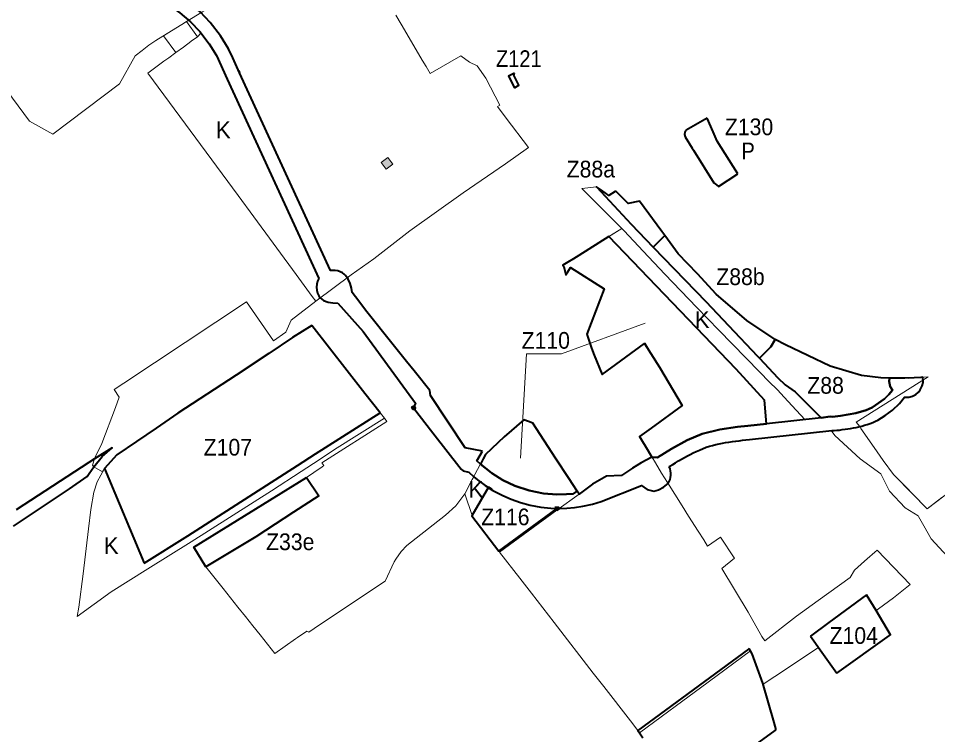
# Model space of a CAD drawing. Extents: x -650276 to -642489, y -1074425 to -1066658.
# Drawn here: x -648043 to -646722, y -1072629 to -1071600 of the extents above; entities that cross this region are included whole.
import ezdxf

# ---------------------------------------------------------------- set-up
doc = ezdxf.new("R2010")
doc.units = 0
doc.header["$LTSCALE"] = 9.6
doc.header["$PDMODE"] = 32
doc.header["$PDSIZE"] = 4.8
for name, color, linetype, lineweight in [('1', 7, 'Continuous', 13), ('43', 7, 'Continuous', 13), ('44', 7, 'Continuous', 40), ('45', 7, 'Continuous', 40), ('46', 7, 'Continuous', 13), ('47', 7, 'Continuous', 13), ('60', 7, 'Continuous', 35)]:
    doc.layers.add(name, color=color, linetype=linetype, lineweight=lineweight)

msp = doc.modelspace()

# ---------------------------------------------------------------- hatches: boundary and pattern name
at = {"layer": '1'}
msp.add_hatch(color=256, dxfattribs=at).paths.add_polyline_path([(-647515.13, -1071817.13), (-647505.54, -1071809.91), (-647512.76, -1071800.33), (-647522.34, -1071807.54)])

# ---------------------------------------------------------------- linework, layer by layer
for points in [[(-648086.68, -1071669.2), (-648027.69, -1071748), (-647993.77, -1071766.7), (-647898.22, -1071694.24), (-647875.8, -1071654.22), (-647865.84, -1071646.51), (-647856.11, -1071638.98), (-647845.78, -1071631.97), (-647823.51, -1071618.28), (-647808.56, -1071609.1), (-647801.84, -1071604.97), (-647778.84, -1071590.84), (-647756.17, -1071577.89), (-647694.65, -1071531.5), (-647658.2, -1071504.43), (-647650.97, -1071499.11), (-647639.66, -1071490.78), (-647632, -1071487.54)], [(-647501.11, -1071595.45), (-647493.6, -1071608.5), (-647471.62, -1071645.45), (-647463.05, -1071660.13), (-647457.62, -1071669.57), (-647451.72, -1071679.52), (-647407.49, -1071654.3), (-647395.07, -1071663.45), (-647384.28, -1071668.72), (-647371.48, -1071686.13), (-647351.64, -1071725.05), (-647355.11, -1071727.05), (-647342.27, -1071743.92), (-647310.23, -1071786.05), (-647343.45, -1071809.51), (-647404.5, -1071850.92), (-647480.76, -1071905.45), (-647532.55, -1071945.64), (-647565.32, -1071968.57), (-647616.12, -1072006.7), (-647651.4, -1072034), (-647659.22, -1072050.95), (-647676.99, -1072063.58), (-647715.48, -1072007.5), (-647891.9, -1072124.43), (-647905.91, -1072133.72), (-647898.74, -1072144.71), (-647903.78, -1072159.62), (-647923.47, -1072211.02), (-647933.11, -1072230.84), (-647933.95, -1072233.18), (-647936.91, -1072242.12), (-647934.9, -1072244.55), (-647922.401, -1072251.989), (-647919.68, -1072247.09), (-647901.91, -1072227.6), (-647845.58, -1072188.94), (-647814.58, -1072167.67), (-647730.53, -1072112.84), (-647683.63, -1072081.94), (-647649.76, -1072059.06), (-647621.97, -1072041.73), (-647545.44, -1072139.35), (-647517.51, -1072174.98), (-647514.05, -1072179.39), (-647607.17, -1072238.79), (-647604.34, -1072242.95), (-647607.02, -1072244.69), (-647619.06, -1072252.92), (-647629.67, -1072259.82), (-647611.51, -1072286.26), (-647648.09, -1072309.95), (-647688.26, -1072336.06), (-647702.35, -1072345.14), (-647716.62, -1072353.95), (-647730.97, -1072362.6), (-647745.32, -1072371.26), (-647759.68, -1072379.91), (-647774.04, -1072388.57), (-647751.23, -1072417.15), (-647749.17, -1072419.72), (-647738.56, -1072433.02), (-647727.94, -1072446.33), (-647717.32, -1072459.63), (-647706.7, -1072472.93), (-647696.09, -1072486.23), (-647685.46, -1072499.54), (-647674.85, -1072512.84), (-647645.17, -1072492.03), (-647642.28, -1072490), (-647628.89, -1072480.61), (-647626.19, -1072482.38), (-647610.9, -1072471.66), (-647516.33, -1072408.76), (-647503.64, -1072381.33), (-647501.08, -1072377.59), (-647493.33, -1072366.28), (-647485.08, -1072357.8), (-647471.76, -1072347.31), (-647429.53, -1072314.04), (-647415.04, -1072300.91), (-647401.88, -1072283.4), (-647395.732, -1072271.563), (-647391.3, -1072263.04), (-647372.1, -1072226.89), (-647345.589, -1072201.74), (-647317.33, -1072176.99), (-647310.33, -1072179.58), (-647304.32, -1072181.81), (-647271.38, -1072232.23), (-647251.85, -1072262.12), (-647240.55, -1072279.42)], [(-647801.84, -1071604.97), (-647808.56, -1071609.1), (-647823.51, -1071618.28), (-647835.178, -1071625.453), (-647817.33, -1071649.51)], [(-647817.33, -1071649.51), (-647806.35, -1071641.47), (-647795.76, -1071633.72), (-647794.98, -1071633.15), (-647786.1, -1071626.65), (-647801.84, -1071604.97)], [(-647119.07, -1072253.56), (-647128.07, -1072238.83), (-647138.65, -1072221.5), (-647151.05, -1072201.21), (-647134.17, -1072188.95), (-647089.54, -1072156.53), (-647105.82, -1072129.3), (-647122.33, -1072101.34), (-647142.77, -1072067), (-647143.76, -1072067.69), (-647204.38, -1072111.87), (-647216.23, -1072084.14), (-647219.64, -1072074.29), (-647226.41, -1072054.11), (-647201.53, -1071988.71), (-647249.92, -1071958.12), (-647253.85, -1071964.38), (-647256.53, -1071968.64), (-647259.7, -1071957.06), (-647261.12, -1071954.82), (-647253.67, -1071950.76), (-647176.32, -1071902.3), (-647194.128, -1071884.447), (-647209.94, -1071868.59), (-647233.81, -1071844.66), (-647212.66, -1071842.15), (-647194.96, -1071854.93), (-647184.81, -1071848.61), (-647167.15, -1071866.22), (-647151.07, -1071863.08), (-647095.51, -1071938.39), (-647067.53, -1071967.54), (-647040.89, -1071996.58), (-646996.8, -1072034.35), (-646956.04, -1072061.95), (-646876.83, -1072100.12), (-646868.61, -1072102.6), (-646832.01, -1072113.66), (-646806.87, -1072116.94), (-646771.31, -1072117.49), (-646763.93, -1072117.61), (-646736.02, -1072115.38), (-646839.631, -1072180.339), (-646834.279, -1072186.818), (-646832.718, -1072189.697), (-646813.516, -1072217.078), (-646800.76, -1072235.668), (-646785.958, -1072255.505), (-646766.842, -1072275.063)], [(-646737.449, -1072305.019), (-646643.55, -1072233.5), (-646593.85, -1072195.48), (-646592.2, -1072196.17), (-646539.94, -1072160.83), (-646555.49, -1072138.17), (-646563.11, -1072143.03), (-646577.08, -1072118.7)], [(-647240.55, -1072279.42), (-647237.6, -1072283.78), (-647269.52, -1072307.17), (-647351.86, -1072367.52), (-647323.06, -1072404.65), (-647306.23, -1072426.35), (-647273.75, -1072468.22), (-647217.32, -1072540.99), (-647202.22, -1072560.47), (-647164.01, -1072609.74), (-647153.2, -1072623.68), (-647150.75, -1072626.84), (-647088.39, -1072580.86), (-647063.38, -1072562.42), (-646991.24, -1072509.24), (-646989.01, -1072513.62), (-646973.68, -1072555.68), (-646973.066, -1072556.947), (-646956.61, -1072546.07), (-646893.64, -1072504.45), (-646898.1, -1072498.02), (-646905.18, -1072487.8), (-646878.91, -1072468.54), (-646850.71, -1072447.86), (-646824.42, -1072428.58), (-646810.77, -1072451.09), (-646807.63, -1072448.81), (-646785.86, -1072433.01), (-646761.676, -1072413.971), (-646809.315, -1072364.299), (-646812.476, -1072367.094), (-646823.75, -1072377.06), (-646827.49, -1072380.37), (-646841.82, -1072393.03), (-646848.37, -1072403.6), (-646893.97, -1072436.54), (-646925.22, -1072459.03), (-646970.68, -1072494.71), (-646975.12, -1072488.48), (-646994.61, -1072453.36), (-647032.76, -1072390.75), (-647014.14, -1072376.08), (-647014.73, -1072375.41), (-647034.39, -1072345.9), (-647052.94, -1072358.64), (-647058.5, -1072349.78), (-647066.38, -1072337.31), (-647080.27, -1072315.34), (-647089.59, -1072300.59), (-647110.55, -1072267.42), (-647119.07, -1072253.56)], [(-646766.842, -1072275.063), (-646758.684, -1072283.41), (-646737.449, -1072305.019)]]:
    msp.add_lwpolyline(points, dxfattribs=at)
msp.add_lwpolyline([(-647515.13, -1071817.13), (-647505.54, -1071809.91), (-647512.76, -1071800.33), (-647522.34, -1071807.54)], close=True, dxfattribs=at)
at = {"layer": '44'}
msp.add_line((-646978.602, -1072088.66), (-646951.95, -1072116.84), dxfattribs=at)
for points in [[(-647725.629, -1071678.373), (-647735.352, -1071657.117), (-647741.34, -1071644.028), (-647753.065, -1071625.201), (-647767.784, -1071606.225), (-647782.408, -1071590.847), (-647798.911, -1071576.526), (-647817.375, -1071563.458), (-647834.953, -1071553.406)], [(-647847.103, -1071569.497), (-647828.141, -1071580.34), (-647811.272, -1071592.28), (-647796.24, -1071605.324), (-647782.97, -1071619.278)], [(-647782.97, -1071619.278), (-647769.498, -1071636.647), (-647758.994, -1071653.513), (-647743.48, -1071687.426), (-647611.514, -1071974.086)], [(-647563.77, -1071994.38), (-647564.751, -1071987.939), (-647566.62, -1071981.3), (-647569.422, -1071974.943), (-647573.283, -1071969.627), (-647575.415, -1071967.709), (-647577.881, -1071965.979), (-647581.036, -1071964.346), (-647584.363, -1071963.196), (-647588.064, -1071962.51), (-647591.518, -1071962.387), (-647594.731, -1071962.714), (-647725.614, -1071678.405), (-647726.774, -1071675.885), (-647725.629, -1071678.373)], [(-647611.514, -1071974.086), (-647613.455, -1071978.031), (-647614.654, -1071982.238), (-647615.083, -1071986.65), (-647614.76, -1071990.762), (-647613.637, -1071995.081), (-647611.779, -1071999.069), (-647609.808, -1072001.962)], [(-647542.57, -1072021.99), (-647558.97, -1072000.62), (-647563.77, -1071994.38)], [(-647609.808, -1072001.962), (-647604.924, -1072005.628), (-647598.384, -1072007.852), (-647591.564, -1072009.255), (-647584.202, -1072009.747)], [(-647584.202, -1072009.747), (-647547.916, -1072050.439), (-647473.022, -1072153.375), (-647475.57, -1072159.74)], [(-647452.23, -1072134.91), (-647472.86, -1072109.13), (-647474.72, -1072106.81), (-647485.6, -1072093.2), (-647504.73, -1072069.29), (-647542.57, -1072021.99)], [(-646790.432, -1072129.195), (-646791.977, -1072122.305), (-646791.84, -1072117.172), (-646804.27, -1072116.98), (-646832.01, -1072113.66), (-646876.83, -1072100.12), (-646941.054, -1072069.172), (-646956.04, -1072061.95), (-646962.041, -1072072.379), (-646978.602, -1072088.66)], [(-646951.95, -1072116.84), (-646941.45, -1072126.84), (-646927.14, -1072136.74), (-646891.05, -1072172.79), (-646890.044, -1072174.056), (-646876.712, -1072172.592), (-646873.495, -1072172.799), (-646862.09, -1072171.444), (-646840.102, -1072167.623), (-646825.169, -1072163.164), (-646816.74, -1072159.571), (-646799, -1072147), (-646792.58, -1072140.847), (-646787.481, -1072134.643), (-646790.432, -1072129.195)], [(-646808.466, -1072177.78), (-646797.713, -1072171.151), (-646787.223, -1072163.402), (-646777.129, -1072153.576), (-646770.057, -1072144.677), (-646763.959, -1072144.535), (-646758.736, -1072143.137), (-646753.929, -1072140.612), (-646750.164, -1072137.467), (-646747.39, -1072134.069), (-646744.554, -1072128.415), (-646743.411, -1072123.612), (-646743.596, -1072115.985), (-646746.547, -1072116.221), (-646756.298, -1072117), (-646769.668, -1072117.517), (-646783.449, -1072117.302), (-646791.84, -1072117.172)], [(-646791.84, -1072117.172), (-646791.977, -1072122.305), (-646790.432, -1072129.195)], [(-647376.68, -1072222.29), (-647401.221, -1072217.342), (-647451.21, -1072142.08), (-647452.23, -1072134.91)], [(-646790.432, -1072129.195), (-646787.481, -1072134.643), (-646792.58, -1072140.847), (-646799, -1072147), (-646816.74, -1072159.571), (-646825.169, -1072163.164), (-646840.102, -1072167.623), (-646862.09, -1072171.444), (-646873.495, -1072172.799), (-646876.712, -1072172.592), (-646890.044, -1072174.056), (-646968.503, -1072182.672)], [(-647475.57, -1072159.74), (-647447.73, -1072195.72), (-647407.34, -1072247.93)], [(-646835.538, -1072187.097), (-646831.517, -1072186.103), (-646827.501, -1072184.997), (-646823.496, -1072183.769), (-646819.509, -1072182.408), (-646815.549, -1072180.906), (-646811.621, -1072179.254), (-646808.466, -1072177.78)], [(-646968.503, -1072182.672), (-646995.137, -1072185.597), (-647010.148, -1072187.308), (-647035.515, -1072191.104), (-647060.973, -1072197.439), (-647082.249, -1072206.591), (-647104.989, -1072219.005), (-647124.81, -1072231.168), (-647133, -1072230.754), (-647148.71, -1072238.76)], [(-647017.46, -1072208.427), (-647012.612, -1072207.773), (-647007.734, -1072207.162), (-647002.826, -1072206.583), (-646997.894, -1072206.024), (-646992.937, -1072205.475), (-646874.517, -1072192.471), (-646871.271, -1072192.675)], [(-646871.271, -1072192.675), (-646867.371, -1072192.234), (-646867.32, -1072192.228), (-646863.448, -1072191.771), (-646859.506, -1072191.276), (-646855.545, -1072190.741), (-646851.567, -1072190.155)], [(-646851.567, -1072190.155), (-646847.575, -1072189.507), (-646843.569, -1072188.789), (-646843.535, -1072188.782), (-646839.556, -1072187.988), (-646835.538, -1072187.097)], [(-648050.276, -1072330.025), (-647969.894, -1072276.479), (-647944.45, -1072258.458), (-647941.77, -1072254.45), (-647934.9, -1072244.55), (-647923.16, -1072229.85), (-647908.5, -1072217.29), (-647933.95, -1072233.18), (-647942.21, -1072238.54), (-648046.69, -1072306.3)], [(-647108.131, -1072244.373), (-647103.164, -1072241.306), (-647098.944, -1072238.718), (-647094.737, -1072236.177), (-647090.531, -1072233.695), (-647086.322, -1072231.285), (-647082.102, -1072228.962), (-647077.867, -1072226.739), (-647073.611, -1072224.631), (-647069.33, -1072222.651), (-647064.868, -1072220.746), (-647054.841, -1072216.479), (-647050.344, -1072215.107), (-647045.786, -1072213.858), (-647041.174, -1072212.723), (-647036.512, -1072211.693), (-647031.807, -1072210.758), (-647027.061, -1072209.91), (-647022.278, -1072209.136), (-647017.46, -1072208.427)], [(-647240.55, -1072279.42), (-647246.206, -1072283.328), (-647255.671, -1072284.192), (-647269.579, -1072284.489), (-647288.769, -1072283.003), (-647309.416, -1072278.875), (-647330.032, -1072271.935), (-647347.382, -1072263.623), (-647363.317, -1072253.632), (-647363.786, -1072253.254), (-647379.422, -1072240.675), (-647384.567, -1072236.256), (-647376.68, -1072222.29)], [(-647148.71, -1072238.76), (-647160.91, -1072246.82), (-647176.7, -1072257.24), (-647198.3, -1072258.09), (-647218.35, -1072269.67), (-647237.6, -1072283.78), (-647240.55, -1072279.42)], [(-647407.34, -1072247.93), (-647404.45, -1072250.66), (-647396.25, -1072252.14), (-647389.072, -1072258.845)], [(-647389.072, -1072258.845), (-647383.813, -1072263.219), (-647372.858, -1072271.363), (-647361.521, -1072278.584), (-647347.369, -1072286.111)], [(-647205.975, -1072294.599), (-647148.171, -1072271.47), (-647139.697, -1072277.484), (-647130.12, -1072279.44), (-647123.774, -1072277.899)], [(-647123.774, -1072277.899), (-647116.323, -1072273.885), (-647109.812, -1072268.588)], [(-647347.369, -1072286.111), (-647335.382, -1072291.341), (-647321.953, -1072296.073), (-647308.157, -1072299.786), (-647292.715, -1072302.646), (-647278.108, -1072304.147), (-647271.395, -1072304.452), (-647269.52, -1072307.17), (-647265.793, -1072304.439)], [(-647265.793, -1072304.439), (-647255.16, -1072304.123), (-647244.428, -1072303.192), (-647232.368, -1072301.4), (-647218.5, -1072298.335), (-647205.975, -1072294.599)]]:
    msp.add_lwpolyline(points, dxfattribs=at)
msp.add_arc((-647130.12, -1072255.012), 24.428, 326.23773, 25.81772, dxfattribs=at)
msp.add_point((-647475.57, -1072159.74), dxfattribs=at)
at = {"layer": '45'}
for points in [[(-647330.34, -1071678.82), (-647339.211, -1071683.431), (-647330.73, -1071700.09)], [(-647330.73, -1071700.09), (-647324.21, -1071696.2), (-647331.65, -1071681.7), (-647330.34, -1071678.82)], [(-647053.43, -1071743.63), (-647083.97, -1071760.74), (-647084.95, -1071761.98), (-647085.71, -1071763.75), (-647086.19, -1071766.95), (-647085.25, -1071770.69), (-647074.99, -1071786.99), (-647073.19, -1071789.9), (-647044.12, -1071836.68)], [(-647009.514, -1071823.81), (-647016.12, -1071813.35), (-647039.14, -1071776.9), (-647044.83, -1071763.37), (-647053.43, -1071743.63)], [(-647044.12, -1071836.68), (-647040.2, -1071839.6), (-647037.23, -1071841.82), (-647009.514, -1071823.81)], [(-647184.81, -1071848.61), (-647185.62, -1071849.12), (-647194.96, -1071854.93), (-647205.62, -1071847.24), (-647212.66, -1071842.15), (-647163.08, -1071896.13), (-647131.146, -1071929.146)], [(-647131.146, -1071929.146), (-647114.479, -1071912.479), (-647118.79, -1071906.59), (-647151.07, -1071863.08), (-647167.15, -1071866.22), (-647184.81, -1071848.61)], [(-646996.8, -1072034.35), (-647040.89, -1071996.58), (-647067.53, -1071967.54), (-647095.51, -1071938.39), (-647114.479, -1071912.479), (-647131.146, -1071929.146), (-647101.07, -1071960.24)], [(-647101.07, -1071960.24), (-647055.16, -1072007.74), (-647023.04, -1072041.63), (-646981.35, -1072085.77), (-646978.602, -1072088.66), (-646962.041, -1072072.379), (-646956.04, -1072061.95), (-646996.8, -1072034.35)], [(-647621.97, -1072041.73), (-647649.76, -1072059.06), (-647683.63, -1072081.94), (-647730.53, -1072112.84), (-647814.58, -1072167.67), (-647845.58, -1072188.94), (-647901.91, -1072227.6), (-647919.68, -1072247.09), (-647862.615, -1072383.084)], [(-647523.71, -1072167.071), (-647545.44, -1072139.35), (-647621.97, -1072041.73)], [(-647862.615, -1072383.084), (-647800.2, -1072343.615), (-647642.504, -1072242.974), (-647616.719, -1072226.154), (-647523.71, -1072167.071)], [(-647362.702, -1072277.035), (-647367.686, -1072273.861), (-647391.761, -1072315.201), (-647353.041, -1072365.971), (-647270.701, -1072305.621), (-647266.974, -1072302.89), (-647272.576, -1072302.903)], [(-646824.42, -1072428.58), (-646878.91, -1072468.54), (-646905.18, -1072487.8)], [(-646824.42, -1072428.58), (-646878.91, -1072468.54), (-646905.18, -1072487.8)], [(-646867.283, -1072540.984), (-646791.569, -1072487.198), (-646790.354, -1072486.136), (-646810.77, -1072451.09), (-646824.42, -1072428.58)], [(-646867.283, -1072540.984), (-646791.569, -1072487.198), (-646790.354, -1072486.136), (-646810.77, -1072451.09), (-646824.42, -1072428.58)], [(-646905.18, -1072487.8), (-646898.1, -1072498.02), (-646893.64, -1072504.45), (-646867.283, -1072540.984)], [(-646905.18, -1072487.8), (-646898.1, -1072498.02), (-646893.64, -1072504.45), (-646867.283, -1072540.984)], [(-646993.05, -1072505.68), (-646994.2, -1072506.52), (-647153.2, -1072623.68), (-647150.75, -1072626.84), (-647146.21, -1072634.02)], [(-646954.617, -1072622.388), (-646957.5, -1072612.09), (-646973.68, -1072555.68), (-646989.01, -1072513.62), (-646991.24, -1072509.24), (-646993.05, -1072505.68)], [(-647192.069, -1072916.856), (-647177.144, -1072871.095), (-647160.08, -1072833.974), (-647140.764, -1072806.081), (-647083.498, -1072727.769), (-647028.234, -1072676.101), (-646956.061, -1072623.348), (-646954.617, -1072622.388)]]:
    msp.add_lwpolyline(points, dxfattribs=at)
for points in [[(-647226.41, -1072054.11), (-647219.64, -1072074.29), (-647216.23, -1072084.14), (-647204.78, -1072110.92), (-647204.38, -1072111.87), (-647143.76, -1072067.69), (-647122.33, -1072101.34), (-647089.54, -1072156.53), (-647134.17, -1072188.95), (-647151.05, -1072201.21), (-647138.65, -1072221.5), (-647133, -1072230.754), (-647124.81, -1072231.168), (-647104.989, -1072219.005), (-647082.249, -1072206.591), (-647060.973, -1072197.439), (-647035.515, -1072191.104), (-647010.148, -1072187.308), (-646995.137, -1072185.597), (-646968.503, -1072182.672), (-646971.283, -1072148.82), (-647011.762, -1072104.502), (-647194.903, -1071913.941), (-647238.1, -1071941), (-647245.71, -1071945.77), (-647253.67, -1071950.76), (-647261.12, -1071954.82), (-647259.7, -1071957.06), (-647256.53, -1071968.64), (-647253.85, -1071964.38), (-647249.92, -1071958.12), (-647201.53, -1071988.71)], [(-647226.41, -1072054.11), (-647219.64, -1072074.29), (-647216.23, -1072084.14), (-647204.78, -1072110.92), (-647204.38, -1072111.87), (-647143.76, -1072067.69), (-647122.33, -1072101.34), (-647089.54, -1072156.53), (-647134.17, -1072188.95), (-647151.05, -1072201.21), (-647138.65, -1072221.5), (-647133, -1072230.754), (-647124.81, -1072231.168), (-647104.989, -1072219.005), (-647082.249, -1072206.591), (-647060.973, -1072197.439), (-647035.515, -1072191.104), (-647010.148, -1072187.308), (-646995.137, -1072185.597), (-646968.503, -1072182.672), (-646971.283, -1072148.82), (-647011.762, -1072104.502), (-647194.903, -1071913.941), (-647238.1, -1071941), (-647245.71, -1071945.77), (-647253.67, -1071950.76), (-647261.12, -1071954.82), (-647259.7, -1071957.06), (-647256.53, -1071968.64), (-647253.85, -1071964.38), (-647249.92, -1071958.12), (-647201.53, -1071988.71)], [(-647246.563, -1072270.214), (-647251.85, -1072262.12), (-647271.38, -1072232.23), (-647304.32, -1072181.81), (-647310.33, -1072179.58), (-647317.33, -1072176.99), (-647345.42, -1072201.58), (-647372.1, -1072226.89), (-647375.551, -1072233.387), (-647379.422, -1072240.675), (-647363.317, -1072253.632), (-647347.382, -1072263.623), (-647330.032, -1072271.935), (-647309.416, -1072278.875), (-647288.769, -1072283.003), (-647269.579, -1072284.489), (-647255.671, -1072284.192), (-647246.206, -1072283.328), (-647240.55, -1072279.42)], [(-647246.563, -1072270.214), (-647251.85, -1072262.12), (-647271.38, -1072232.23), (-647304.32, -1072181.81), (-647310.33, -1072179.58), (-647317.33, -1072176.99), (-647345.42, -1072201.58), (-647372.1, -1072226.89), (-647375.551, -1072233.387), (-647379.422, -1072240.675), (-647363.317, -1072253.632), (-647347.382, -1072263.623), (-647330.032, -1072271.935), (-647309.416, -1072278.875), (-647288.769, -1072283.003), (-647269.579, -1072284.489), (-647255.671, -1072284.192), (-647246.206, -1072283.328), (-647240.55, -1072279.42)], [(-647629.67, -1072259.82), (-647611.51, -1072286.26), (-647648.09, -1072309.95), (-647688.26, -1072336.06), (-647702.35, -1072345.14), (-647716.62, -1072353.95), (-647730.97, -1072362.6), (-647745.32, -1072371.26), (-647759.68, -1072379.91), (-647774.04, -1072388.57), (-647791.198, -1072360.119)]]:
    msp.add_lwpolyline(points, close=True, dxfattribs=at)
msp.add_arc((-646767.624, -1072120.384), 24.428, 264.28146, 264.89913, dxfattribs=at)
msp.add_arc((-646767.624, -1072120.384), 24.428, 264.28146, 264.89913, dxfattribs=at)
at = {"layer": '46'}
msp.add_lwpolyline([(-647321.863, -1072232.262), (-647313.149, -1072082.081), (-647262.801, -1072082.081), (-647142.741, -1072038.48)], dxfattribs=at)
msp.add_lwpolyline([(-647321.863, -1072232.262), (-647313.149, -1072082.081), (-647262.801, -1072082.081), (-647142.741, -1072038.48)], dxfattribs=at)
at = {"layer": '47'}
msp.add_line((-647391.346, -1072314.489), (-647368.024, -1072274.442), dxfattribs=at)
msp.add_lwpolyline([(-647817.33, -1071649.51), (-647806.35, -1071641.47), (-647795.76, -1071633.72), (-647794.98, -1071633.15), (-647786.1, -1071626.65), (-647781.134, -1071621.645), (-647769.498, -1071636.647), (-647758.889, -1071653.742), (-647743.48, -1071687.426), (-647611.514, -1071974.086), (-647613.455, -1071978.031), (-647614.654, -1071982.238), (-647615.083, -1071986.65), (-647614.76, -1071990.762), (-647613.637, -1071995.081), (-647611.779, -1071999.069), (-647609.808, -1072001.962), (-647616.12, -1072006.7), (-647621.06, -1072000), (-647644.38, -1071968.3), (-647705.291, -1071885.501), (-647727.85, -1071854.86), (-647857.52, -1071678.92), (-647834.345, -1071661.969), (-647827.42, -1071656.89)], close=True, dxfattribs=at)
for points in [[(-646913.373, -1072176.618), (-646931.653, -1072156.802), (-646942.78, -1072144.74), (-646952.48, -1072134.22), (-646964.8, -1072121.83), (-646977.59, -1072108.96), (-646978.45, -1072108.09), (-647036.8, -1072048.41), (-647068.31, -1072015.68), (-647114.59, -1071967.77), (-647145.38, -1071935), (-647173.14, -1071905.45), (-647174.57, -1071904.06), (-647176.32, -1071902.3), (-647194.902, -1071913.942), (-647011.762, -1072104.502)], [(-647011.762, -1072104.502), (-646971.283, -1072148.82), (-646968.503, -1072182.672), (-646913.373, -1072176.618)], [(-647795.4, -1072352.415), (-647679.66, -1072279.15), (-647637.082, -1072251.377), (-647611.306, -1072234.563), (-647589.02, -1072219.66), (-647517.51, -1072174.98), (-647523.71, -1072167.071), (-647616.719, -1072226.154), (-647642.504, -1072242.974), (-647800.888, -1072344.051), (-647810.794, -1072350.315), (-647862.615, -1072383.084), (-647919.68, -1072247.09)], [(-646716.167, -1072288.809), (-646737.449, -1072305.019), (-646738.951, -1072303.49), (-646758.684, -1072283.41), (-646785.958, -1072255.505), (-646800.76, -1072235.668), (-646813.508, -1072217.089), (-646813.516, -1072217.078), (-646832.718, -1072189.697), (-646834.279, -1072186.818), (-646835.199, -1072187.013), (-646835.538, -1072187.097), (-646839.556, -1072187.988), (-646843.535, -1072188.782), (-646843.569, -1072188.789), (-646847.575, -1072189.507), (-646851.567, -1072190.155), (-646855.545, -1072190.741), (-646859.506, -1072191.276), (-646863.448, -1072191.771), (-646867.32, -1072192.228), (-646867.371, -1072192.234), (-646871.271, -1072192.675), (-646873.131, -1072192.558), (-646875.509, -1072192.58), (-646870.21, -1072199.51), (-646833.75, -1072233.32), (-646803.98, -1072254.74), (-646791.59, -1072279.78), (-646769.24, -1072303.65), (-646750.58, -1072315.02), (-646750.12, -1072315.82), (-646742.32, -1072329.62), (-646731.82, -1072348.2), (-646696.83, -1072385.81)], [(-647919.68, -1072247.09), (-647930.36, -1072266.38), (-647934.86, -1072280.99), (-647939.26, -1072306.1), (-647942.54, -1072333.82), (-647950.2, -1072398.61), (-647956.786, -1072446.511)], [(-647389.072, -1072258.845), (-647391.3, -1072263.04), (-647401.88, -1072283.4), (-647391.346, -1072314.489)], [(-647368.024, -1072274.442), (-647372.858, -1072271.363), (-647372.858, -1072271.363), (-647383.813, -1072263.219), (-647389.072, -1072258.845)], [(-647956.786, -1072446.511), (-647958.82, -1072459.74), (-647910.27, -1072424.51), (-647857.52, -1072391.14), (-647795.4, -1072352.415)]]:
    msp.add_lwpolyline(points, dxfattribs=at)

# ---------------------------------------------------------------- texts
at = {"layer": '43'}
for p in [(-647759.879, -1071772.452), (-647759.879, -1071772.452), (-647071.498, -1072045.307), (-647396.507, -1072288.9), (-647920.872, -1072369.761)]:
    msp.add_text('K', height=24, dxfattribs=at).set_placement(p)
at = {"layer": '44', "width": 0.95}
msp.add_text('Z88', height=24, dxfattribs=at).set_placement((-646909.741, -1072139.634))
msp.add_text('Z88', height=24, dxfattribs=at).set_placement((-646909.741, -1072139.634))
at = {"layer": '46'}
for s, width, p in [('Z121', 0.9, (-647357.291, -1071670.187)), ('Z130', 0.95, (-647028.202, -1071768.178)), ('Z88a', 0.95, (-647255.564, -1071828.861)), ('Z88b', 0.95, (-647040.507, -1071983.505)), ('Z110', 0.95, (-647320.328, -1072074.974)), ('Z110', 0.95, (-647320.328, -1072074.974)), ('Z107', 0.95, (-647777.22, -1072228.544)), ('Z116', 0.95, (-647378.432, -1072328.636)), ('Z33e', 0.95, (-647687.519, -1072364.366)), ('Z104', 0.95, (-646877.745, -1072499.058)), ('Z104', 0.95, (-646877.745, -1072499.058))]:
    msp.add_text(s, height=24, dxfattribs=dict(at, width=width)).set_placement(p)
at = {"layer": '60', "width": 0.9}
msp.add_text('P', height=24, dxfattribs=at).set_placement((-647004.438, -1071802.773))

doc.saveas('drawing.dxf')
